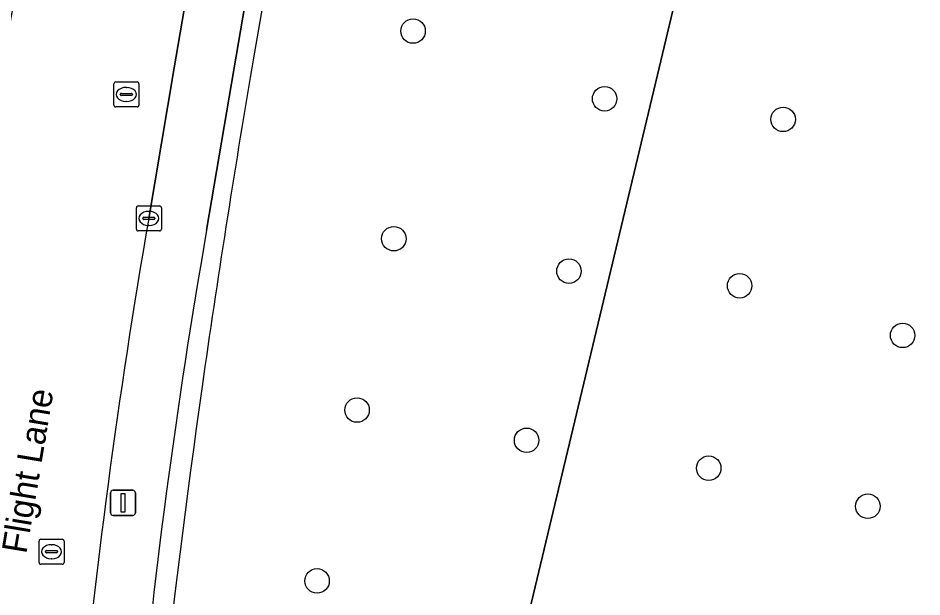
# Model space of a CAD drawing. Extents: x 155018 to 156648, y 383979 to 385733.
# Drawn here: x 156051.04 to 156087.13, y 384728.89 to 384751.98 of the extents above; entities that cross this region are included whole.
import ezdxf

# ---------------------------------------------------------------- set-up
doc = ezdxf.new("R2010")
doc.units = 0
for name, color, linetype in [('IMGEO_Berm_groen', 7, 'Continuous'), ('IMGEO_Boom', 7, 'Continuous'), ('IMGEO_Groenvoorziening', 7, 'Continuous'), ('IMGEO_Kolk', 7, 'Continuous'), ('IMGEO_Lichtmast', 7, 'Continuous'), ('IMGEO_Openbare_ruimte_label', 7, 'Continuous'), ('IMGEO_OVBaan_gesloten', 7, 'Continuous'), ('IMGEO_Rioolput', 7, 'Continuous'), ('IMGEO_Voetpad_gesloten', 7, 'Continuous')]:
    doc.layers.add(name, color=color, linetype=linetype)

msp = doc.modelspace()

# ---------------------------------------------------------------- linework, layer by layer
at = {"layer": 'IMGEO_Berm_groen'}
msp.add_lwpolyline([(156061.239, 384754.919), (156060.512, 384754.988), (156059.662, 384750), (156058.567, 384743.52)], dxfattribs=at)
for centre, radius, start, end in [((156558.592, 384665.026), 505.412, 169.75479, 170.32096), ((156529.863, 384670.019), 476.252, 170.33199, 171.88058), ((156313.724, 384698.98), 259.015, 170.09828, 174.7994), ((156463.482, 384679.821), 409.152, 171.92655, 179.49049)]:
    msp.add_arc(centre, radius, start, end, dxfattribs=at)
at = {"layer": 'IMGEO_Boom'}
for centre in [(156066.808, 384751.462), (156074.457, 384748.761), (156081.584, 384747.938), (156066.04, 384743.179), (156073.033, 384741.884), (156079.848, 384741.302), (156086.355, 384739.322), (156064.573, 384736.343), (156071.341, 384735.136), (156078.613, 384734.024), (156084.966, 384732.506), (156062.976, 384729.527)]:
    msp.add_circle(centre, 0.489, dxfattribs=at)
at = {"layer": 'IMGEO_Groenvoorziening'}
for points in [[(156087.406, 384775.429), (156085.725, 384758.647), (156091.02, 384758.062), (156090.429, 384752.008), (156077.442, 384753.408), (156076.635, 384750), (156071.116, 384726.893)], [(156076.635, 384750), (156077.442, 384753.408), (156065.919, 384754.472), (156061.239, 384754.919)], [(156071.116, 384726.893), (156076.635, 384750)]]:
    msp.add_lwpolyline(points, dxfattribs=at)
for centre, radius, start, end in [((156558.592, 384665.026), 505.412, 169.75479, 170.32096), ((156529.863, 384670.019), 476.252, 170.33199, 171.88058), ((156463.482, 384679.821), 409.152, 171.92655, 179.49049)]:
    msp.add_arc(centre, radius, start, end, dxfattribs=at)
at = {"layer": 'IMGEO_Kolk'}
for p, q in [((156055.76, 384743.563), (156055.76, 384744.415)), ((156055.835, 384744.489), (156056.687, 384744.489)), ((156056.248, 384744.269), (156056.273, 384744.269)), ((156056.761, 384744.415), (156056.761, 384743.563)), ((156056.019, 384743.983), (156056.019, 384743.995)), ((156056.457, 384743.946), (156056.059, 384743.946)), ((156056.062, 384744.032), (156056.46, 384744.032)), ((156056.503, 384743.995), (156056.503, 384743.983)), ((156056.687, 384743.489), (156055.835, 384743.489)), ((156056.271, 384743.709), (156056.246, 384743.709))]:
    msp.add_line(p, q, dxfattribs=at)
for points in [[(156055.76, 384743.563), (156055.76, 384744.415)], [(156055.835, 384744.489), (156056.687, 384744.489)], [(156056.761, 384744.415), (156056.761, 384743.563)], [(156056.687, 384743.489), (156055.835, 384743.489)]]:
    msp.add_lwpolyline(points, dxfattribs=at)
for centre, radius, start, end in [((156055.837, 384744.413), 0.0765, 91.552, 178.448), ((156055.837, 384744.413), 0.0765, 91.552, 178.448), ((156056.685, 384744.413), 0.0765, 1.552, 88.448), ((156056.685, 384744.413), 0.0765, 1.552, 88.448), ((156056.059, 384743.992), 0.0403, 85.8775, 175.7526), ((156056.056, 384743.982), 0.0366, 178.938, 274.7102), ((156056.46, 384743.989), 0.043, 264.8664, 352.4533), ((156056.464, 384743.994), 0.0386, 1.7309, 96.639), ((156055.837, 384743.565), 0.0765, 181.552, 268.448), ((156055.837, 384743.565), 0.0765, 181.552, 268.448), ((156056.685, 384743.565), 0.0765, 271.552, 358.448), ((156056.685, 384743.565), 0.0765, 271.552, 358.448)]:
    msp.add_arc(centre, radius, start, end, dxfattribs=at)
for centre, major_axis, ratio, start_param, end_param in [((156056.247, 384743.989), (-0.387, 0.002), 0.722429, 4.712389, 7.853982), ((156056.272, 384743.989), (-0.39, 0.002), 0.717154, 1.570796, 4.712389)]:
    msp.add_ellipse(centre, major_axis=major_axis, ratio=ratio, start_param=start_param, end_param=end_param, dxfattribs=at)
at = {"layer": 'IMGEO_Lichtmast'}
for p, q in [((156054.73, 384732.241), (156054.73, 384733.041)), ((156054.73, 384733.041), (156054.73, 384732.241)), ((156054.83, 384733.141), (156055.62, 384733.141)), ((156055.62, 384733.141), (156054.83, 384733.141)), ((156055.72, 384733.041), (156055.72, 384732.241)), ((156055.72, 384732.241), (156055.72, 384733.041)), ((156055.62, 384732.141), (156054.83, 384732.141)), ((156054.83, 384732.141), (156055.62, 384732.141))]:
    msp.add_line(p, q, dxfattribs=at)
msp.add_lwpolyline([(156055.15, 384733.016), (156055.3, 384733.016), (156055.3, 384732.266), (156055.15, 384732.266), (156055.15, 384733.016)], dxfattribs=at)
for centre, start, end in [((156054.83, 384733.041), 90, 180), ((156054.83, 384733.041), 90, 180), ((156055.62, 384733.041), 0, 90), ((156055.62, 384733.041), 360, 90), ((156054.83, 384732.241), 180, 270), ((156054.83, 384732.241), 180, 270), ((156055.62, 384732.241), 270, 0), ((156055.62, 384732.241), 270, 0)]:
    msp.add_arc(centre, 0.1, start, end, dxfattribs=at)
at = {"layer": 'IMGEO_OVBaan_gesloten'}
msp.add_lwpolyline([(156056.254, 384743.988), (156057.275, 384750), (156058.16, 384755.212), (156053.991, 384755.61), (156051.467, 384755.851), (156050.375, 384750), (156049.014, 384742.478)], dxfattribs=at)
msp.add_arc((156317.892, 384698.53), 265.558, 170.14356, 174.77443, dxfattribs=at)
at = {"layer": 'IMGEO_Rioolput'}
for p, q in [((156054.861, 384748.508), (156054.861, 384749.36)), ((156054.936, 384749.434), (156055.788, 384749.434)), ((156055.862, 384749.36), (156055.862, 384748.508)), ((156055.12, 384748.928), (156055.12, 384748.94)), ((156055.558, 384748.891), (156055.16, 384748.891)), ((156055.163, 384748.977), (156055.561, 384748.977)), ((156055.349, 384749.214), (156055.374, 384749.214)), ((156055.604, 384748.94), (156055.604, 384748.928)), ((156055.372, 384748.654), (156055.347, 384748.654)), ((156055.788, 384748.434), (156054.936, 384748.434)), ((156051.874, 384730.265), (156051.874, 384731.117)), ((156051.949, 384731.191), (156052.801, 384731.191)), ((156052.362, 384730.971), (156052.387, 384730.971)), ((156052.875, 384731.117), (156052.875, 384730.265)), ((156052.133, 384730.685), (156052.133, 384730.697)), ((156052.571, 384730.648), (156052.173, 384730.648)), ((156052.176, 384730.734), (156052.574, 384730.734)), ((156052.617, 384730.697), (156052.617, 384730.685)), ((156052.801, 384730.191), (156051.949, 384730.191)), ((156052.385, 384730.411), (156052.36, 384730.411))]:
    msp.add_line(p, q, dxfattribs=at)
for points in [[(156054.861, 384748.508), (156054.861, 384749.36)], [(156054.936, 384749.434), (156055.788, 384749.434)], [(156055.862, 384749.36), (156055.862, 384748.508)], [(156055.788, 384748.434), (156054.936, 384748.434)], [(156051.874, 384730.265), (156051.874, 384731.117)], [(156051.949, 384731.191), (156052.801, 384731.191)], [(156052.875, 384731.117), (156052.875, 384730.265)], [(156052.801, 384730.191), (156051.949, 384730.191)]]:
    msp.add_lwpolyline(points, dxfattribs=at)
for centre, radius, start, end in [((156054.938, 384749.358), 0.0765, 91.552, 178.448), ((156054.938, 384749.358), 0.0765, 91.552, 178.448), ((156055.786, 384749.358), 0.0765, 1.552, 88.448), ((156055.786, 384749.358), 0.0765, 1.552, 88.448), ((156055.16, 384748.937), 0.0403, 85.8775, 175.7526), ((156055.157, 384748.927), 0.0366, 178.938, 274.7102), ((156055.561, 384748.934), 0.043, 264.8664, 352.4533), ((156055.565, 384748.939), 0.0386, 1.7309, 96.639), ((156054.938, 384748.51), 0.0765, 181.552, 268.448), ((156054.938, 384748.51), 0.0765, 181.552, 268.448), ((156055.786, 384748.51), 0.0765, 271.552, 358.448), ((156055.786, 384748.51), 0.0765, 271.552, 358.448), ((156051.951, 384731.115), 0.0765, 91.552, 178.448), ((156051.951, 384731.115), 0.0765, 91.552, 178.448), ((156052.799, 384731.115), 0.0765, 1.552, 88.448), ((156052.799, 384731.115), 0.0765, 1.552, 88.448), ((156052.173, 384730.694), 0.0403, 85.8775, 175.7526), ((156052.17, 384730.684), 0.0366, 178.938, 274.7102), ((156052.574, 384730.691), 0.043, 264.8664, 352.4533), ((156052.578, 384730.696), 0.0386, 1.7309, 96.639), ((156051.951, 384730.267), 0.0765, 181.552, 268.448), ((156051.951, 384730.267), 0.0765, 181.552, 268.448), ((156052.799, 384730.267), 0.0765, 271.552, 358.448), ((156052.799, 384730.267), 0.0765, 271.552, 358.448)]:
    msp.add_arc(centre, radius, start, end, dxfattribs=at)
for centre, major_axis, ratio, start_param, end_param in [((156055.348, 384748.934), (-0.387, 0.002), 0.722429, 4.712389, 7.853982), ((156055.373, 384748.934), (-0.39, 0.002), 0.717154, 1.570796, 4.712389), ((156052.361, 384730.691), (-0.387, 0.002), 0.722429, 4.712389, 7.853982), ((156052.386, 384730.691), (-0.39, 0.002), 0.717154, 1.570796, 4.712389)]:
    msp.add_ellipse(centre, major_axis=major_axis, ratio=ratio, start_param=start_param, end_param=end_param, dxfattribs=at)
at = {"layer": 'IMGEO_Voetpad_gesloten'}
msp.add_lwpolyline([(156058.567, 384743.52), (156059.662, 384750), (156060.512, 384754.988), (156058.16, 384755.212), (156057.275, 384750), (156056.254, 384743.988)], dxfattribs=at)
for centre, radius, start, end in [((156317.892, 384698.53), 265.558, 170.14356, 174.77443), ((156313.724, 384698.98), 259.015, 170.09828, 174.7994)]:
    msp.add_arc(centre, radius, start, end, dxfattribs=at)

# ---------------------------------------------------------------- texts
at = {"layer": 'IMGEO_Openbare_ruimte_label'}
msp.add_text('Flight Lane', height=1, rotation=80.5, dxfattribs=at).set_placement((156051.366, 384730.578))

doc.saveas('drawing.dxf')
